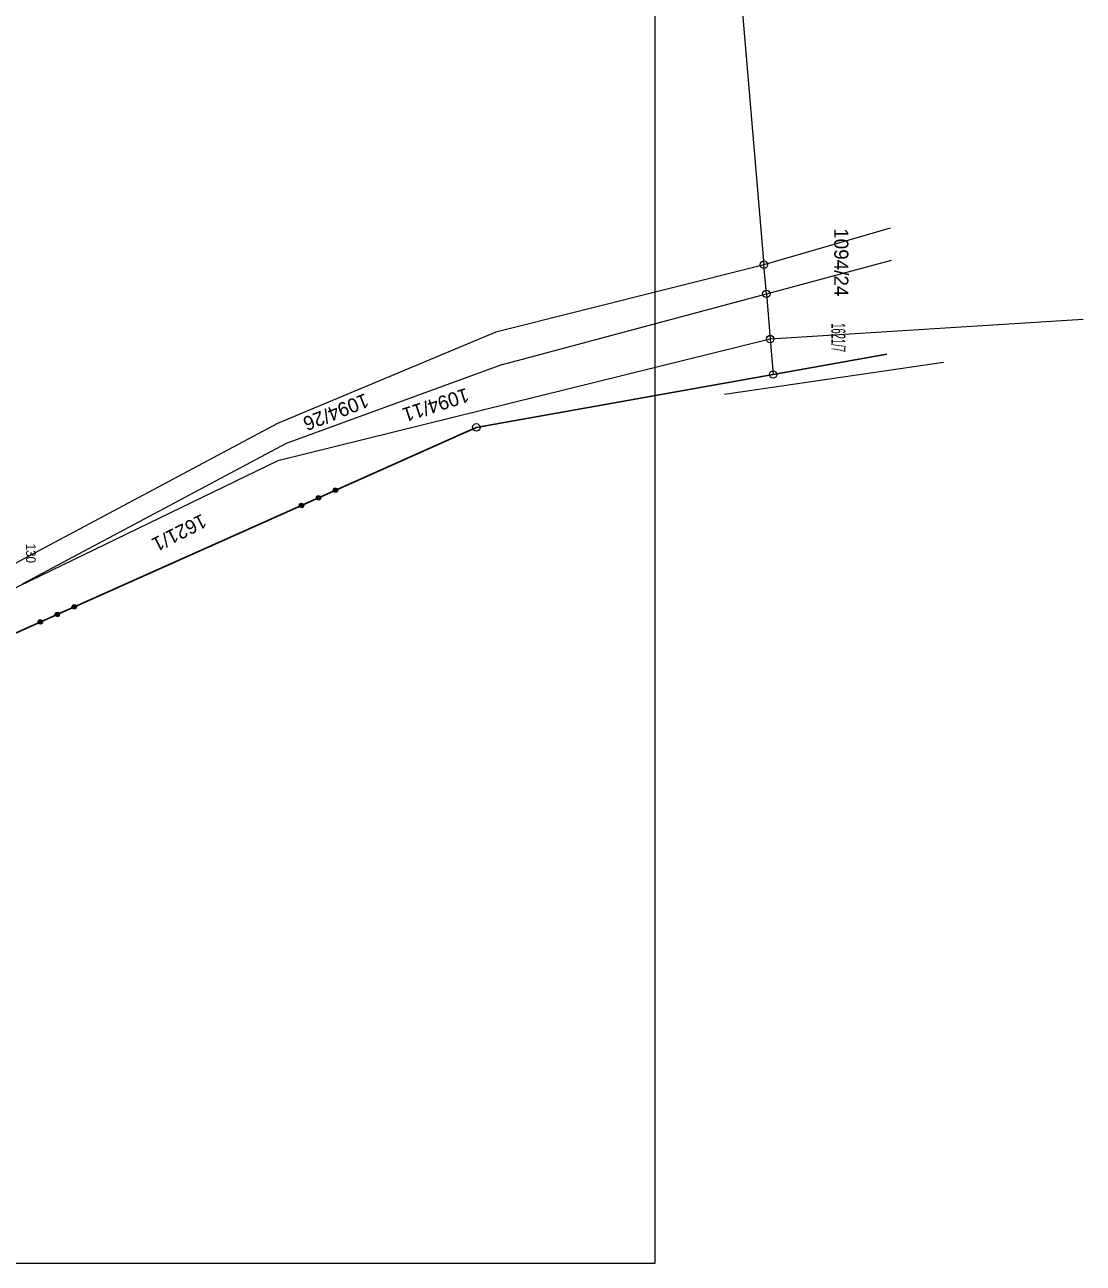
# Model space of a CAD drawing. Extents: x -687355 to -686912, y -958376 to -957235.
# Drawn here: x -687075.7 to -686933.4, y -958310.3 to -958143.7 of the extents above; entities that cross this region are included whole.
import ezdxf
from ezdxf.enums import TextEntityAlignment as Align

# ---------------------------------------------------------------- set-up
doc = ezdxf.new("R2010")
doc.units = 0
doc.header["$LTSCALE"] = 0.76
doc.layers.add('1', color=7, linetype='Continuous', lineweight=13)
doc.layers.add('28', color=7, linetype='Continuous', lineweight=13)
doc.layers.add('14', color=7, linetype='Continuous')

msp = doc.modelspace()

# ---------------------------------------------------------------- linework, layer by layer
at = {"layer": '1'}
for p, q in [((-686979.52, -958138.48), (-686976.35, -958176.02)), ((-686959.39, -958171.11), (-686976.35, -958176.02)), ((-686976.02, -958179.93), (-686976.35, -958176.02)), ((-686976.02, -958179.93), (-686975.51, -958186.02)), ((-686933.41, -958183.37), (-686975.51, -958186.02)), ((-686975.51, -958186.02), (-687041.72, -958202.4)), ((-686975.51, -958186.02), (-686975.1, -958190.79)), ((-686952.22, -958189.16), (-686981.66, -958193.47)), ((-687041.77, -958197.37), (-687077.13, -958216.26)), ((-687041.72, -958202.4), (-687077.96, -958219.99)), ((-687036.319, -958207.188), (-687036.156, -958207.554)), ((-687034.036, -958206.169), (-687033.873, -958206.535)), ((-687038.602, -958208.208), (-687038.439, -958208.573)), ((-687069.163, -958221.85), (-687069, -958222.215)), ((-687073.729, -958223.888), (-687073.566, -958224.253)), ((-687071.446, -958222.869), (-687071.283, -958223.234))]:
    msp.add_line(p, q, dxfattribs=at)
for points in [[(-687287.96, -957310.331), (-687287.96, -958310.331), (-686990.96, -958310.331), (-686990.96, -957310.331)], [(-687036.471, -958207.585), (-687036.552, -958207.402), (-687036.451, -958207.138), (-687036.268, -958207.056), (-687036.004, -958207.158), (-687035.923, -958207.34), (-687036.024, -958207.604), (-687036.206, -958207.686)], [(-687034.188, -958206.566), (-687034.269, -958206.383), (-687034.168, -958206.119), (-687033.986, -958206.037), (-687033.721, -958206.138), (-687033.64, -958206.321), (-687033.741, -958206.585), (-687033.924, -958206.667)], [(-687038.754, -958208.604), (-687038.835, -958208.421), (-687038.734, -958208.157), (-687038.551, -958208.075), (-687038.287, -958208.177), (-687038.206, -958208.359), (-687038.307, -958208.623), (-687038.489, -958208.705)], [(-687069.315, -958222.246), (-687069.396, -958222.064), (-687069.295, -958221.799), (-687069.113, -958221.718), (-687068.848, -958221.819), (-687068.767, -958222.002), (-687068.868, -958222.266), (-687069.051, -958222.347)], [(-687073.881, -958224.284), (-687073.962, -958224.102), (-687073.861, -958223.838), (-687073.678, -958223.756), (-687073.414, -958223.857), (-687073.333, -958224.04), (-687073.434, -958224.304), (-687073.616, -958224.385)], [(-687071.598, -958223.265), (-687071.679, -958223.083), (-687071.578, -958222.819), (-687071.396, -958222.737), (-687071.131, -958222.838), (-687071.05, -958223.021), (-687071.151, -958223.285), (-687071.334, -958223.366)]]:
    msp.add_lwpolyline(points, close=True, dxfattribs=at)
for points in [[(-687011.5, -958189.43), (-686976.02, -958179.93), (-686959.21, -958175.43)], [(-686976.35, -958176.02), (-686977.2, -958176.27), (-687012.41, -958185.11), (-687041.77, -958197.37)], [(-687011.5, -958189.43), (-687040.6, -958200.06), (-687076.107, -958219.001)], [(-687036.461, -958207.361), (-687036.379, -958207.544), (-687036.247, -958207.595), (-687036.41, -958207.229), (-687036.228, -958207.148), (-687036.065, -958207.513), (-687036.014, -958207.381), (-687036.096, -958207.198)], [(-687034.178, -958206.342), (-687034.096, -958206.525), (-687033.964, -958206.575), (-687034.127, -958206.21), (-687033.945, -958206.129), (-687033.782, -958206.494), (-687033.731, -958206.362), (-687033.813, -958206.179)], [(-687038.744, -958208.38), (-687038.662, -958208.563), (-687038.53, -958208.614), (-687038.693, -958208.248), (-687038.511, -958208.167), (-687038.347, -958208.532), (-687038.297, -958208.4), (-687038.378, -958208.217)], [(-687069.305, -958222.023), (-687069.224, -958222.205), (-687069.091, -958222.256), (-687069.254, -958221.891), (-687069.072, -958221.809), (-687068.909, -958222.174), (-687068.858, -958222.042), (-687068.94, -958221.86)], [(-687073.871, -958224.061), (-687073.789, -958224.244), (-687073.657, -958224.294), (-687073.82, -958223.929), (-687073.638, -958223.847), (-687073.475, -958224.213), (-687073.424, -958224.081), (-687073.506, -958223.898)], [(-687071.588, -958223.042), (-687071.506, -958223.225), (-687071.374, -958223.275), (-687071.537, -958222.91), (-687071.355, -958222.828), (-687071.192, -958223.194), (-687071.141, -958223.061), (-687071.223, -958222.879)]]:
    msp.add_lwpolyline(points, dxfattribs=at)
at = {"layer": '1', "lineweight": 25}
msp.add_lwpolyline([(-687086.19, -958229.67), (-687015.02, -958197.9), (-686975.1, -958190.79), (-686959.82, -958188.07)], dxfattribs=at)
at = {"layer": '1'}
for centre, radius in [((-686976.35, -958176.02), 0.5), ((-686976.35, -958176.02), 0.01), ((-686976.02, -958179.93), 0.5), ((-686976.02, -958179.93), 0.01), ((-686975.51, -958186.02), 0.5), ((-686975.51, -958186.02), 0.01), ((-686975.1, -958190.79), 0.5), ((-686975.1, -958190.79), 0.01), ((-687015.02, -958197.9), 0.5), ((-687015.02, -958197.9), 0.01)]:
    msp.add_circle(centre, radius, dxfattribs=at)
at = {"layer": '28'}
for centre, radius in [((-686976.35, -958176.02), 0.5), ((-686976.35, -958176.02), 0.01), ((-686976.02, -958179.93), 0.5), ((-686976.02, -958179.93), 0.01), ((-686975.51, -958186.02), 0.5), ((-686975.51, -958186.02), 0.01), ((-686975.1, -958190.79), 0.5), ((-686975.1, -958190.79), 0.01), ((-687015.02, -958197.9), 0.5), ((-687015.02, -958197.9), 0.01)]:
    msp.add_circle(centre, radius, dxfattribs=at)

# ---------------------------------------------------------------- texts
at = {"layer": '1', "width": 0.9}
msp.add_text('130', height=1.3, rotation=270, dxfattribs=at).set_placement((-687075.561, -958213.537))
at = {"layer": '14'}
for s, rotation, p in [('1094/24', 270, (-686966.89, -958175.696)), ('1094/11', 198, (-687020.752, -958193.983)), ('1094/26', 201.6, (-687034.234, -958194.963)), ('1621/1', 207, (-687055.378, -958211.219))]:
    msp.add_text(s, height=1.9, rotation=rotation, dxfattribs=at).set_placement(p, align=Align.CENTER)
at = {"layer": '14', "width": 0.5}
msp.add_text('1621/7', height=1.9, rotation=270, dxfattribs=at).set_placement((-686967.28, -958185.828), align=Align.CENTER)

doc.saveas('drawing.dxf')
